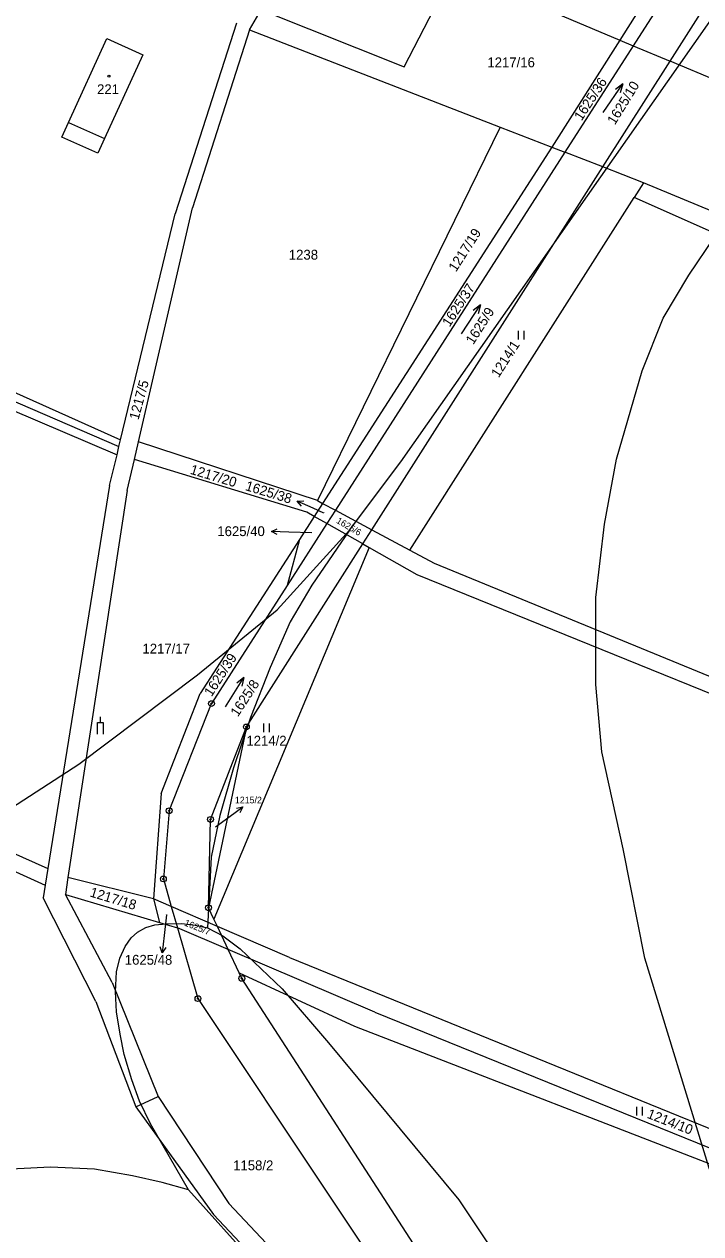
# Model space of a CAD drawing. Extents: x -546762 to -540209, y -1046851 to -1035694.
# Drawn here: x -543423.7 to -543306.6, y -1041617.8 to -1041408.5 of the extents above; entities that cross this region are included whole.
import ezdxf

# ---------------------------------------------------------------- set-up
doc = ezdxf.new("R2010")
doc.units = 0
for name, color, linetype in [('Vrstva 1', 7, 'Continuous'), ('Vrstva 16', 7, 'Continuous'), ('Vrstva 18', 7, 'Continuous'), ('Vrstva 19', 7, 'Continuous'), ('Vrstva 24', 7, 'Continuous'), ('Vrstva 25', 7, 'Continuous'), ('Vrstva 3', 7, 'Continuous'), ('Vrstva 37', 7, 'Continuous'), ('Vrstva 4', 7, 'Continuous'), ('Vrstva 52', 7, 'Continuous'), ('Vrstva 6', 7, 'Continuous')]:
    doc.layers.add(name, color=color, linetype=linetype)

msp = doc.modelspace()

# ---------------------------------------------------------------- linework, layer by layer
at = {"layer": 'Vrstva 1'}
for p, q in [((-543416.03, -1041425.48), (-543409.43, -1041410.95)), ((-543409.43, -1041410.95), (-543403.21, -1041413.78)), ((-543403.21, -1041413.78), (-543409.82, -1041428.29)), ((-543417.19, -1041428.04), (-543416.03, -1041425.48)), ((-543410.96, -1041430.79), (-543417.19, -1041428.04)), ((-543409.82, -1041428.29), (-543410.96, -1041430.79))]:
    msp.add_line(p, q, dxfattribs=at)
for points in [[(-543288.43, -1041365.54), (-543318.34, -1041412.21)], [(-543293.78, -1041368.69), (-543320.67, -1041411.23)], [(-543311.97, -1041414.88), (-543282.4, -1041368.38)], [(-543384.76, -1041409.46), (-543382.73, -1041406.01)], [(-543386.99, -1041408.3), (-543397.58, -1041441.33)], [(-543384.76, -1041409.46), (-543394.6, -1041440.25)], [(-543320.67, -1041411.23), (-543332.4, -1041429.78)], [(-543318.34, -1041412.21), (-543330.16, -1041430.65)], [(-543318.34, -1041412.21), (-543311.97, -1041414.88)], [(-543323.62, -1041433.19), (-543311.97, -1041414.88)], [(-543332.4, -1041429.78), (-543372.08, -1041491.43)], [(-543330.16, -1041430.65), (-543369.87, -1041492.61)], [(-543323.62, -1041433.19), (-543330.16, -1041430.65)], [(-543363.57, -1041495.98), (-543323.62, -1041433.19)], [(-543316.56, -1041435.93), (-543323.62, -1041433.19)], [(-543316.56, -1041435.93), (-543318.17, -1041438.46)], [(-543304.76, -1041440.82), (-543316.56, -1041435.93)], [(-543246.9, -1041470.14), (-543318.17, -1041438.46)], [(-543403.95, -1041480.78), (-543394.6, -1041440.25)], [(-543407.04, -1041480.43), (-543397.58, -1041441.33)], [(-543407.32, -1041481.58), (-543407.04, -1041480.43)], [(-543404.65, -1041483.8), (-543403.95, -1041480.78)], [(-543407.66, -1041483.01), (-543407.32, -1041481.58)], [(-543408.95, -1041488.33), (-543407.66, -1041483.01)], [(-543405.89, -1041489.21), (-543404.65, -1041483.8)], [(-543408.95, -1041488.33), (-543419.62, -1041554.62)], [(-543405.89, -1041489.21), (-543416.15, -1041556.17)], [(-543372.08, -1041491.43), (-543373.53, -1041493.69)], [(-543369.87, -1041492.61), (-543371.35, -1041494.92)], [(-543369.87, -1041492.61), (-543363.57, -1041495.98)], [(-543371.35, -1041494.92), (-543378.2, -1041505.61)], [(-543373.53, -1041493.69), (-543376.08, -1041497.66)], [(-543365.13, -1041498.43), (-543371.35, -1041494.92)], [(-543365.13, -1041498.43), (-543363.57, -1041495.98)], [(-543376.08, -1041497.66), (-543393.25, -1041524.31)], [(-543385.27, -1041530.1), (-543365.13, -1041498.43)], [(-543378.2, -1041505.61), (-543391.31, -1041526.07)], [(-543400.03, -1041541.62), (-543393.25, -1041524.31)], [(-543398.63, -1041544.6), (-543391.31, -1041526.07)], [(-543385.27, -1041530.1), (-543391.82, -1041561.39)], [(-543391.49, -1041546.1), (-543385.27, -1041530.1)], [(-543400.03, -1041541.62), (-543401.33, -1041559.83)], [(-543398.63, -1041544.6), (-543399.64, -1041556.42)], [(-543391.82, -1041561.39), (-543391.49, -1041546.1)], [(-543419.62, -1041554.62), (-543420.08, -1041557.49)], [(-543416.15, -1041556.17), (-543416.6, -1041559.11)], [(-543420.08, -1041557.49), (-543420.44, -1041559.7)], [(-543399.64, -1041556.42), (-543398.27, -1041561.16)], [(-543411.31, -1041577.62), (-543420.44, -1041559.7)], [(-543408.51, -1041574.36), (-543416.6, -1041559.11)], [(-543416.6, -1041559.11), (-543400.31, -1041563.96)], [(-543401.33, -1041559.83), (-543400.31, -1041563.96)], [(-543398.27, -1041561.16), (-543397.19, -1041564.89)], [(-543390.3, -1041564.62), (-543398.27, -1041561.16)], [(-543390.88, -1041563.39), (-543391.82, -1041561.39)], [(-543400.31, -1041563.96), (-543397.19, -1041564.89)], [(-543390.3, -1041564.62), (-543390.88, -1041563.39)], [(-543388.41, -1041568.64), (-543390.3, -1041564.62)], [(-543397.19, -1041564.89), (-543393.66, -1041577.13)], [(-543388.41, -1041568.64), (-543397.19, -1041564.89)], [(-543386.53, -1041572.65), (-543388.41, -1041568.64)], [(-543386.07, -1041573.62), (-543386.53, -1041572.65)], [(-543408.51, -1041574.36), (-543400.55, -1041594.08)], [(-543352.54, -1041625.45), (-543386.07, -1041573.62)], [(-543393.66, -1041577.13), (-543347.39, -1041646.58)], [(-543411.31, -1041577.62), (-543404.38, -1041595.84)], [(-543404.38, -1041595.84), (-543400.55, -1041594.08)], [(-543404.38, -1041595.84), (-543390.96, -1041614.47)], [(-543400.55, -1041594.08), (-543388.33, -1041612.61)], [(-543388.33, -1041612.61), (-543371.71, -1041630.24)], [(-543390.96, -1041614.47), (-543376.34, -1041630.09)]]:
    msp.add_lwpolyline(points, dxfattribs=at)
at = {"layer": 'Vrstva 16'}
for p, q in [((-543373.73, -1041492.25), (-543376.46, -1041491.02)), ((-543377.94, -1041496.37), (-543380.94, -1041496.26)), ((-543388.32, -1041545.73), (-543385.89, -1041543.96)), ((-543399.49, -1041566.23), (-543399.83, -1041569.21))]:
    msp.add_line(p, q, dxfattribs=at)
for points in [[(-543375.76, -1041491.88), (-543376.46, -1041491.02), (-543375.35, -1041490.97)], [(-543371.85, -1041493.1), (-543373.73, -1041492.25)], [(-543379.96, -1041496.8), (-543380.94, -1041496.26), (-543379.92, -1041495.8)], [(-543373.93, -1041496.51), (-543377.94, -1041496.37)], [(-543390.6, -1041547.39), (-543388.32, -1041545.73)], [(-543387, -1041544.15), (-543385.89, -1041543.96), (-543386.41, -1041544.96)], [(-543399.08, -1041562.61), (-543399.49, -1041566.23)], [(-543399.22, -1041568.27), (-543399.83, -1041569.21), (-543400.21, -1041568.16)]]:
    msp.add_lwpolyline(points, dxfattribs=at)
at = {"layer": 'Vrstva 24'}
for centre, radius in [((-543391.31, -1041526.07), 0.5), ((-543391.31, -1041526.07), 0.1), ((-543385.27, -1041530.1), 0.5), ((-543385.27, -1041530.1), 0.1), ((-543398.63, -1041544.6), 0.5), ((-543398.63, -1041544.6), 0.1), ((-543391.49, -1041546.1), 0.5), ((-543391.49, -1041546.1), 0.1), ((-543399.64, -1041556.42), 0.5), ((-543399.64, -1041556.42), 0.1), ((-543391.82, -1041561.39), 0.5), ((-543391.82, -1041561.39), 0.1), ((-543386.07, -1041573.62), 0.5), ((-543386.07, -1041573.62), 0.1), ((-543393.66, -1041577.13), 0.5), ((-543393.66, -1041577.13), 0.1)]:
    msp.add_circle(centre, radius, dxfattribs=at)
at = {"layer": 'Vrstva 25'}
for p, q in [((-543338.2, -1041463.06), (-543338.2, -1041461.56)), ((-543337.2, -1041463.06), (-543337.2, -1041461.56)), ((-543382.28, -1041531), (-543382.28, -1041529.5)), ((-543381.28, -1041531), (-543381.28, -1041529.5)), ((-543317.72, -1041597.37), (-543317.72, -1041595.87)), ((-543316.72, -1041597.37), (-543316.72, -1041595.87))]:
    msp.add_line(p, q, dxfattribs=at)
for points in [[(-543323.53, -1041423.78), (-543320.15, -1041418.82), (-543321.41, -1041419.78)], [(-543320.15, -1041418.82), (-543320.58, -1041420.34)], [(-543348.03, -1041462.1), (-543344.77, -1041457.06), (-543346.01, -1041458.05)], [(-543344.77, -1041457.06), (-543345.17, -1041458.59)], [(-543388.9, -1041526.61), (-543385.72, -1041521.53), (-543386.94, -1041522.53)], [(-543385.72, -1041521.53), (-543386.09, -1041523.06)], [(-543410.53, -1041529.33), (-543410.53, -1041528.33)], [(-543411.03, -1041531.33), (-543411.03, -1041529.33), (-543410.03, -1041529.33), (-543410.03, -1041531.33)]]:
    msp.add_lwpolyline(points, dxfattribs=at)
msp.add_circle((-543409.05, -1041417.5), 0.175, dxfattribs=at)
at = {"layer": 'Vrstva 3'}
for points in [[(-543416.03, -1041425.48), (-543409.43, -1041410.95)], [(-543409.43, -1041410.95), (-543403.21, -1041413.78)], [(-543403.21, -1041413.78), (-543409.82, -1041428.29)], [(-543416.03, -1041425.48), (-543409.82, -1041428.29)]]:
    msp.add_lwpolyline(points, dxfattribs=at)
at = {"layer": 'Vrstva 37'}
msp.add_circle((-543409.05, -1041417.5), 0.175, dxfattribs=at)
at = {"layer": 'Vrstva 4'}
msp.add_line((-543416.03, -1041425.48), (-543409.82, -1041428.29), dxfattribs=at)
at = {"layer": 'Vrstva 52'}
for points in [[(-543367.43, -1041496.06), (-543358.52, -1041484.25), (-543291.66, -1041388.79), (-543235.84, -1041305.67), (-543212.48, -1041277.09), (-543186.52, -1041230.33), (-543130.8, -1041093.03)], [(-543279.72, -1041717.53), (-543282.59, -1041691.08), (-543285.19, -1041670.3), (-543288.89, -1041650.63), (-543295.2, -1041629.11), (-543305.21, -1041606.47), (-543316.34, -1041570.1), (-543320.05, -1041551.18), (-543323.76, -1041534.43), (-543324.82, -1041522.76), (-543324.82, -1041507.71), (-543323.33, -1041494.99), (-543321.22, -1041483.75), (-543316.76, -1041468.48), (-543313.16, -1041459.36), (-543308.71, -1041451.94), (-543304.26, -1041445.37), (-543297.27, -1041438.58), (-543290.06, -1041434.13), (-543281.58, -1041430.31), (-543273.32, -1041428.61), (-543261.66, -1041428.61), (-543251.49, -1041429.89)], [(-543451.59, -1041560.71), (-543414.27, -1041536.56), (-543393.71, -1041521.08), (-543379.94, -1041509.85), (-543367.43, -1041496.06)], [(-543367.43, -1041496.06), (-543373.95, -1041505.55)], [(-543373.95, -1041505.55), (-543377.68, -1041511.92), (-543381.17, -1041519.8), (-543384.56, -1041528.49), (-543387.53, -1041537.18), (-543389.86, -1041545.45), (-543391.35, -1041552.66), (-543392.03, -1041564.88)], [(-543395.27, -1041610.2), (-543401.86, -1041598.79), (-543403.78, -1041594.85), (-543405.09, -1041591.18), (-543406.41, -1041586.81), (-543407.1, -1041583.28), (-543407.72, -1041579.4), (-543407.93, -1041575.94), (-543407.72, -1041572.48), (-543407.17, -1041570.13), (-543406.27, -1041568.12), (-543405.2, -1041566.62), (-543404.1, -1041565.64), (-543402.67, -1041564.8), (-543401.09, -1041564.37), (-543399.15, -1041564.17), (-543396.42, -1041564.13), (-543394.13, -1041564.41)], [(-543394.13, -1041564.41), (-543392.03, -1041564.88)], [(-543392.03, -1041564.88), (-543389.35, -1041566.27), (-543386.34, -1041568.52), (-543379.06, -1041575.45), (-543371.08, -1041584.75), (-543348.51, -1041611.96), (-543326.23, -1041645.4), (-543279.72, -1041717.53)], [(-543395.27, -1041610.2), (-543399.84, -1041608.95), (-543404.96, -1041607.78), (-543411.53, -1041606.67), (-543419.15, -1041606.32), (-543424.89, -1041606.6), (-543429.18, -1041607.22), (-543432.85, -1041608.12), (-543436.24, -1041609.65), (-543439.29, -1041611.58), (-543441.36, -1041613.73), (-543443.71, -1041616.64), (-543445.37, -1041619.55), (-543446.41, -1041622.46), (-543447.04, -1041625.92), (-543447.98, -1041633.54)], [(-543223.2, -1041845.14), (-543243.97, -1041823.94), (-543264.74, -1041802.94), (-543284.03, -1041778.77), (-543300.77, -1041755.44), (-543315.39, -1041730.21), (-543329.12, -1041704.67), (-543339.93, -1041685.8), (-543351.37, -1041667.14), (-543357.73, -1041657.38), (-543366.84, -1041643.81), (-543374.9, -1041633.85), (-543383.59, -1041623.24), (-543395.27, -1041610.2)]]:
    msp.add_lwpolyline(points, dxfattribs=at)
at = {"layer": 'Vrstva 6'}
for points in [[(-543357.98, -1041415.87), (-543350.19, -1041400.77)], [(-543382.73, -1041406.01), (-543357.98, -1041415.87)], [(-543333.94, -1041405.67), (-543320.67, -1041411.23)], [(-543384.76, -1041409.46), (-543341.37, -1041426.3)], [(-543320.67, -1041411.23), (-543318.34, -1041412.21)], [(-543303.72, -1041418.34), (-543311.97, -1041414.88)], [(-543341.37, -1041426.3), (-543372.99, -1041490.94)], [(-543341.37, -1041426.3), (-543332.4, -1041429.78)], [(-543332.4, -1041429.78), (-543330.16, -1041430.65)], [(-543357.01, -1041499.49), (-543318.17, -1041438.46)], [(-543475.09, -1041449.93), (-543407.04, -1041480.43)], [(-543477.03, -1041453.44), (-543407.66, -1041483.01)], [(-543476.08, -1041451.87), (-543407.32, -1041481.58)], [(-543372.99, -1041490.94), (-543403.95, -1041480.78)], [(-543374.83, -1041492.95), (-543404.65, -1041483.8)], [(-543372.99, -1041490.94), (-543372.08, -1041491.43)], [(-543373.53, -1041493.69), (-543374.83, -1041492.95)], [(-543372.08, -1041491.43), (-543369.87, -1041492.61)], [(-543371.35, -1041494.92), (-543373.53, -1041493.69)], [(-543363.57, -1041495.98), (-543357.01, -1041499.49)], [(-543364.02, -1041499.06), (-543390.88, -1041563.39)], [(-543376.08, -1041497.66), (-543378.2, -1041505.61)], [(-543365.13, -1041498.43), (-543364.02, -1041499.06)], [(-543364.02, -1041499.06), (-543355.79, -1041503.7)], [(-543357.01, -1041499.49), (-543352.77, -1041501.76)], [(-543352.77, -1041501.76), (-543256.27, -1041541.4)], [(-543355.79, -1041503.7), (-543265.87, -1041540.2)], [(-543515.78, -1041514.07), (-543420.08, -1041557.49)], [(-543512.04, -1041513.3), (-543419.62, -1041554.62)], [(-543401.33, -1041559.83), (-543416.15, -1041556.17)], [(-543398.27, -1041561.16), (-543401.33, -1041559.83)], [(-543377.84, -1041570.03), (-543390.3, -1041564.62)], [(-543363.02, -1041579.48), (-543388.41, -1041568.64)], [(-543377.84, -1041570.03), (-543279.2, -1041610.14)], [(-543386.53, -1041572.65), (-543366.57, -1041581.92)], [(-543363.02, -1041579.48), (-543288.06, -1041609.9)], [(-543366.57, -1041581.92), (-543297.73, -1041608.54)]]:
    msp.add_lwpolyline(points, dxfattribs=at)

# ---------------------------------------------------------------- texts
at = {"layer": 'Vrstva 16'}
msp.add_text('1625/38', height=1.7, rotation=343.0993, dxfattribs=at).set_placement((-543385.58, -1041489.1))
for s, height, p in [('1625/40', 1.7, (-543390.3, -1041497.08)), ('1215/2', 1.14, (-543387.26, -1041543.33)), ('1625/48', 1.7, (-543406.31, -1041571.26))]:
    msp.add_text(s, height=height, dxfattribs=at).set_placement(p)
at = {"layer": 'Vrstva 18'}
for s, height, p in [('1217/16', 1.7, (-543343.57, -1041415.94)), ('1238', 1.7, (-543377.93, -1041449.23)), ('1625/38', 0.1, (-543372.1, -1041493.1)), ('1625/40', 0.1, (-543374.19, -1041496.51)), ('1217/17', 1.7, (-543403.26, -1041517.4)), ('1214/2', 1.7, (-543385.27, -1041533.34)), ('1215/2', 0.1, (-543390.79, -1041547.39)), ('1625/48', 0.1, (-543399.33, -1041562.61)), ('1158/2', 1.7, (-543387.56, -1041606.83))]:
    msp.add_text(s, height=height, dxfattribs=at).set_placement(p)
for s, height, rotation, p in [('1625/36', 1.7, 56.9073, (-543327.27, -1041425.32)), ('1625/10', 1.7, 58.3048, (-543321.51, -1041426.02)), ('1217/19', 1.7, 57.3368, (-543349, -1041451.46)), ('1625/37', 1.7, 56.9245, (-543350.11, -1041460.99)), ('1625/9', 1.7, 57.4549, (-543346.02, -1041464.06)), ('1214/1', 1.7, 57.37, (-543341.63, -1041469.79)), ('1217/5', 1.7, 74.7929, (-543403.95, -1041477.07)), ('1217/20', 1.7, 343.2126, (-543395.13, -1041486.27)), ('1625/6', 1.14, 329.6588, (-543369.82, -1041494.72)), ('1625/39', 1.7, 57.0094, (-543391.3, -1041524.98)), ('1625/8', 1.7, 56.8997, (-543386.74, -1041528.46)), ('1217/18', 1.7, 343.1572, (-543412.48, -1041559.42)), ('1625/7', 1.14, 338.5087, (-543396.11, -1041564.45)), ('1214/10', 1.7, 338.6526, (-543316.08, -1041597.72))]:
    msp.add_text(s, height=height, rotation=rotation, dxfattribs=at).set_placement(p)
at = {"layer": 'Vrstva 19'}
msp.add_text('221', height=1.7, dxfattribs=at).set_placement((-543411.11, -1041420.59))

doc.saveas('drawing.dxf')
